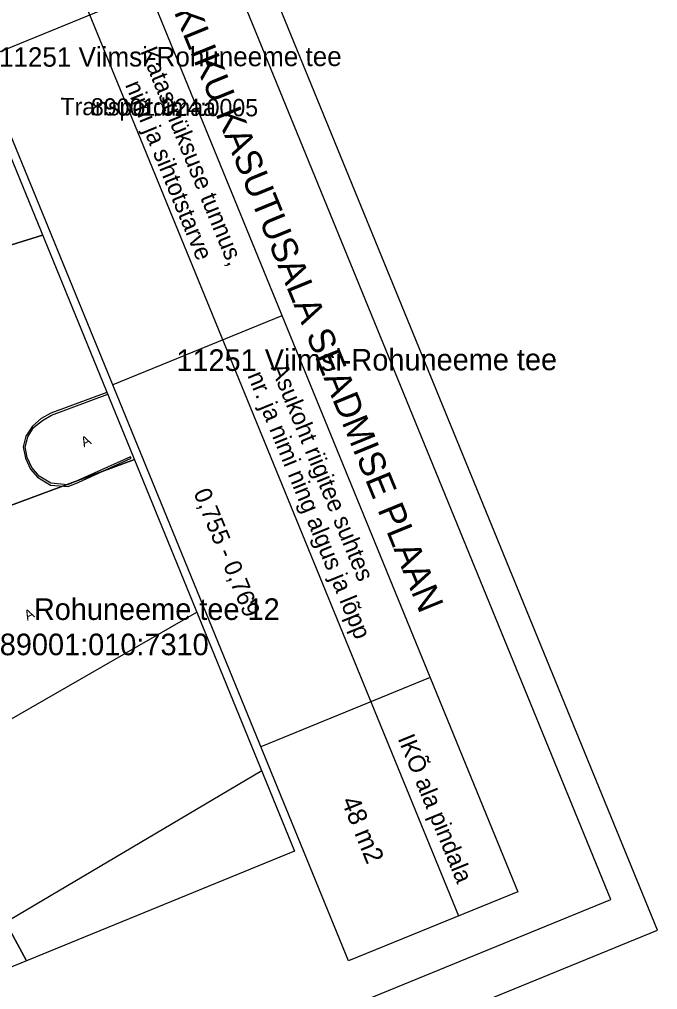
# Model space of a CAD drawing. Extents: x -52238384 to 549205, y 6582846 to 57187752.
# Drawn here: x 546566.4 to 546610.7, y 6597171.2 to 6597238.6 of the extents above; entities that cross this region are included whole.
import ezdxf

# ---------------------------------------------------------------- set-up
doc = ezdxf.new("R2010")
doc.units = 0
for name, color, linetype in [('kaluri tee mõõdistus$0$SITRASS', 7, 'Continuous'), ('kaluri tee mõõdistus$0$TEE', 7, 'Continuous'), ('L_AADRESS', 7, 'Continuous'), ('Level 52', 7, 'Continuous'), ('PIIR', 7, 'Continuous'), ('TUNNUS', 7, 'Continuous'), ('VORMISTUS', 7, 'Continuous')]:
    doc.layers.add(name, color=color, linetype=linetype)

msp = doc.modelspace()

# ---------------------------------------------------------------- linework, layer by layer
at = {"layer": 'kaluri tee mõõdistus$0$SITRASS'}
msp.add_lwpolyline([(546559.046, 6597186.14), (546578.686, 6597197.43)], dxfattribs=at)
at = {"layer": 'kaluri tee mõõdistus$0$TEE'}
for points in [[(546572.442, 6597212.686), (546568.54, 6597211.243), (546567.886, 6597210.867), (546567.273, 6597210.342), (546566.815, 6597209.644), (546566.627, 6597208.898), (546566.79, 6597208.116), (546567.142, 6597207.362), (546567.625, 6597206.802), (546568.528, 6597206.251), (546569.745, 6597206.142), (546570.5, 6597206.446), (546574.135, 6597208.123), (546574.086, 6597208.22), (546570.434, 6597206.57), (546569.706, 6597206.277), (546568.545, 6597206.382), (546567.748, 6597206.875), (546567.237, 6597207.459), (546566.912, 6597208.166), (546566.77, 6597208.896), (546566.951, 6597209.602), (546566.951, 6597209.602), (546567.351, 6597210.243), (546567.978, 6597210.739), (546568.603, 6597211.099), (546572.495, 6597212.559)], [(546583.191, 6597186.42), (546549.279, 6597166.35), (546488.139, 6597150.551)]]:
    msp.add_lwpolyline(points, dxfattribs=at)
at = {"layer": 'Level 52'}
for points in [[(546610.665, 6597175.343), (546570.526, 6597273.43), (546435.57, 6597218.204), (546475.709, 6597120.117)], [(546439.31, 6597217.036), (546477.288, 6597124.229), (546607.423, 6597177.482), (546569.445, 6597270.289)], [(546556.701, 6597251.154), (546585.474, 6597180.84), (546491.483, 6597142.378), (546462.71, 6597212.692)]]:
    msp.add_lwpolyline(points, close=True, dxfattribs=at)
at = {"layer": 'PIIR'}
for points in [[(546524.023, 6597237.782), (546525.91, 6597233.41), (546537.23, 6597214.01), (546552.45, 6597199.91), (546566.856, 6597173.221)], [(546567.974, 6597223.606), (546537.23, 6597214.01), (546525.91, 6597233.41), (546524.023, 6597237.782)], [(546574.352, 6597208.02), (546552.45, 6597199.91), (546537.23, 6597214.01), (546567.974, 6597223.606)], [(546566.856, 6597173.221), (546552.45, 6597199.91), (546574.352, 6597208.02)]]:
    msp.add_lwpolyline(points, dxfattribs=at)
at = {"layer": 'VORMISTUS'}
for p, q in [((546561.583, 6597262.502), (546596.841, 6597176.342)), ((546575.365, 6597240.561), (546563.612, 6597235.752)), ((546584.595, 6597218.006), (546572.842, 6597213.196)), ((546594.875, 6597192.885), (546583.122, 6597188.075))]:
    msp.add_line(p, q, dxfattribs=at)
msp.add_lwpolyline([(546565.697, 6597264.186), (546600.955, 6597178.026), (546589.203, 6597173.216), (546553.945, 6597259.377)], close=True, dxfattribs=at)

# ---------------------------------------------------------------- texts
at = {"layer": 'kaluri tee mõõdistus$0$TEE'}
for p in [(546570.851, 6597208.859), (546566.92, 6597196.828)]:
    msp.add_text('A', height=0.7, rotation=26.8592, dxfattribs=at).set_placement(p)
at = {"layer": 'L_AADRESS'}
for s, height, rotation, p in [('11251 Viimsi-Rohuneeme tee', 1.35, 0.12414, (546564.955, 6597235.283)), ('11251 Viimsi-Rohuneeme tee', 1.5, 0.12414, (546577.264, 6597214.166)), ('Rohuneeme tee 12', 1.5, 360, (546567.372, 6597196.887))]:
    msp.add_text(s, height=height, rotation=rotation, dxfattribs=at).set_placement(p)
at = {"layer": 'Level 52'}
msp.add_text('48 m2', height=1.3001, rotation=292.27796, dxfattribs=at).set_placement((546588.686, 6597184.328))
at = {"layer": 'PIIR'}
for s, p in [('Transpordimaa', (546569.217, 6597231.93)), ('89001:024:0005', (546571.331, 6597231.904))]:
    msp.add_text(s, height=1.2, rotation=359.70214, dxfattribs=at).set_placement(p)
at = {"layer": 'TUNNUS'}
msp.add_text('89001:010:7310', height=1.5, rotation=360, dxfattribs=at).set_placement((546565.006, 6597194.438))
at = {"layer": 'VORMISTUS'}
for s, height, p in [('ISIKLIKU KASUTUSALA SEADMISE PLAAN', 1.8, (546575.958, 6597241.82)), ('Katastriüksuse tunnus,', 1.2, (546574.747, 6597236.372)), ('nimi ja sihtotstarve', 1.2, (546573.688, 6597234.036)), ('Asukoht riigitee suhtes', 1.2, (546583.798, 6597214.407)), ('nr. ja nimi ning algus ja lõpp', 1.2, (546582.177, 6597213.86)), ('0,755 - 0,769', 1.2, (546578.435, 6597205.726)), ('IKÕ ala pindala', 1.2, (546592.61, 6597188.662))]:
    msp.add_text(s, height=height, rotation=292.25515, dxfattribs=at).set_placement(p)

doc.saveas('drawing.dxf')
